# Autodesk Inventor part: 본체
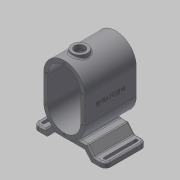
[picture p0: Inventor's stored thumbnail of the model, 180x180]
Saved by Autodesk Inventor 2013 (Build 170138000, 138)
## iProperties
Created: 2016-12
Part Number: 본체
Material: 일반
Document SubType Name: Modeling
Designer: mduedu
Density: 1 g/cm^3
Author: mduedu
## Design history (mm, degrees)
sketch "스케치1"
  geometry: L1 (40, -25)-(40, 25); L2 (-40, 25)-(-40, -25); L3 (-40, -25)-(40, 25); L4 (40, -25)-(-40, 25); L5 (0, 25)-(0, -25); A1 r 40 centre (0, 25) between (40, 25) and (-40, 25); A2 r 40 centre (0, -25) between (-40, -25) and (40, -25); 1 further point
  constraints: 10 end point, 4 point on circle, 3 tangent, 2 centre point, 2 midpoint, 2 parallel, 1 vertical
  dimensions: "d0" = 130 dimension on A2 A1; "d2" = 80 distance between parallel lines of L1 L2
extrude "돌출1" new body sketch "스케치1" stored distance "d3" = 100; taper "d4" = 0 deg
feature "쉘1" dims "d5" = 8
sketch "스케치15"
  geometry: L1 (-35, -64.5)-(35, -64.5); L2 (-35, -64.5)-(-47.586, -79.5); L3 (-47.586, -79.5)-(-70, -79.5); L4 (0, -64.5)-(0, 0); L5 (35, -64.5)-(47.586, -79.5); L6 (47.586, -79.5)-(70, -79.5); L7 (70, -89.5)-(42.923, -89.5); L8 (42.923, -89.5)-(30.337, -74.5); L9 (30.337, -74.5)-(-30.337, -74.5); L10 (-30.337, -74.5)-(-42.923, -89.5); L11 (-42.923, -89.5)-(-70, -89.5); L12 (-70, -79.5)-(-70, -89.5); L13 (70, -79.5)-(70, -89.5); A1 r 40 centre (0, -25) between (-40, -25) and (40, -25) reference; 1 further point
  constraints: 26 end point, 2 parallel, 2 perpendicular, 2 symmetric about line, 1 coincident, 1 horizontal, 1 midpoint, 1 vertical, 4 other
  dimensions: "d83" = 10 distance between parallel lines of L9 L1; "d85" = 140 distance between parallel lines of L13 L12; "d86" = 70 distance of L1.start L1.end; "d87" = 25 distance between parallel lines of L11 L1; "d88" = 130 deg angle of L1 L2; "d106" = 0.5 distance edge to line of A1 L1
extrude "돌출6" new body sketch "스케치15" stored distance "d89" = 80; taper "d90" = 0 deg
fillet "모깎기13" dims "d101" = 3
fillet "모깎기15" dims "d103" = 3
fillet "모깎기16" dims "d104" = 10
fillet "모깎기17" dims "d105" = 3
feature "결합2"
  node "솔리드2"
fillet "모깎기18" dims "d107" = 3
sketch "스케치16"
  geometry: L1 (8.015, 67)-(8.015, 7); L2 (14.015, 67)-(14.015, 7); A1 r 10 centre (11.015, 67) between (21.015, 67) and (11.015, 77) reference; A2 r 10 centre (11.015, 7) between (11.015, -3) and (21.015, 7) reference; A3 r 3 centre (11.015, 67) between (8.015, 67) and (14.015, 67); A4 r 3 centre (11.015, 7) between (8.015, 7) and (14.015, 7); 1 further point
  constraints: 4 end point, 4 point on circle, 4 tangent, 2 centre point, 2 coincident
  dimensions: "d108" = 6 diameter of A3; "d109" = 6 diameter of A4
extrude "돌출7" cut sketch "스케치16" stored distance "d110" = 80; taper "d111" = 0 deg
node "작업 평면1"
sketch "스케치9"
  geometry: 1 further point
sketch "스케치7"
  geometry: L1 (40, 50)-(-40, 50) reference; C1 r 15 at (0, 20); 1 further point
  constraints: 1 centre point, 1 vertical alignment
  dimensions: "d40" = 30 diameter of C1; "d41" = 30 distance from line of C1.centre L1
extrude "돌출4" join sketch "스케치7" stored distance "d42" = 80; taper "d43" = 0 deg
hole "구멍2" diameter "d46" = 20; stored, may be unused: countersink angle "d50" = 90 deg, drill point angle "d52" = 118 deg; dims "d44" = 10, "d45" = 10, "d47" = 6, "d48" = 4, "d49" = 2, "d51" = 8
fillet "모깎기4" dims "d53" = 3
node "작업 평면2"
sketch "스케치8"
  geometry: C1 r 15 at (0, 0) reference; C2 r 15 at (0, 0); 1 further point
  constraints: 1 centre point, 1 coincident
  dimensions: "d55" = 30 diameter of C2
extrude "돌출5" cut sketch "스케치8" stored distance "d56" = 80; taper "d57" = 0 deg
chamfer "모따기1" distance "d58" = 1; stored, may be unused: second distance "d59" = 2, angle "d60" = 45 deg
sketch "스케치10"
  geometry: 2 further points
  constraints: 1 coincident, 1 other
feature "엠보싱1" sketch "스케치10" dims "d0" = 130, "d2" = 80, "d61" = 0.5, "d62" = 0
sketch "스케치11"
  geometry: 1 further point
  constraints: 1 other
hole "구멍3" sketch "스케치11" at (0, 60) diameter "d63" = 3.242; stored, may be unused: countersink angle "d67" = 90 deg, drill point angle "d69" = 120 deg; dims "d64" = 8.6, "d65" = 4, "d66" = 2, "d68" = 10.6
sketch "스케치12"
  geometry: 1 further point
  constraints: 1 other
hole "구멍5" sketch "스케치12" at (0, 60) diameter "d70" = 3.242; stored, may be unused: countersink angle "d74" = 90 deg, drill point angle "d76" = 120 deg; dims "d71" = 8.6, "d72" = 4, "d73" = 2, "d75" = 10.6
node "솔리드1"
mirror "대칭2"
pattern_linear "직사각형 패턴1"
pattern_linear "직사각형 패턴2"
sketch "스케치13"
  geometry: L1 (-40, 25)-(-40, -25) reference; L2 (40, -25)-(40, 25) reference; L3 (35, 25)-(35, -25); L4 (-35, -25)-(-35, 25); A1 r 40 centre (0, 25) between (40, 25) and (-40, 25) reference; A2 r 40 centre (0, -25) between (-40, -25) and (40, -25) reference; A3 r 35 centre (0, 25) between (35, 25) and (-35, 25); A4 r 35 centre (0, -25) between (-35, -25) and (35, -25); 2 further points
  constraints: 5 point on circle, 4 end point, 2 centre point, 3 other
  dimensions: "d77" = 5 distance between parallel lines of L3 L2
sketch "스케치14"
  geometry: L1 (-40, 25)-(-40, -25) reference; L2 (40, -25)-(40, 25) reference; L3 (35, 25)-(35, -25); L4 (-35, -25)-(-35, 25); A1 r 40 centre (0, 25) between (40, 25) and (-40, 25) reference; A2 r 40 centre (0, -25) between (-40, -25) and (40, -25) reference; A3 r 35 centre (0, 25) between (35, 25) and (-35, 25); A4 r 35 centre (0, -25) between (-35, -25) and (35, -25); 2 further points
  constraints: 5 point on circle, 4 end point, 2 centre point, 3 other
  dimensions: "d80" = 5 distance between parallel lines of L2 L3
other parameters: "d54" = -8
